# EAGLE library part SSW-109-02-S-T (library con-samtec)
THROUGH-HOLE .025" SQ POST SOCKET Source: Samtec SSW.pdf
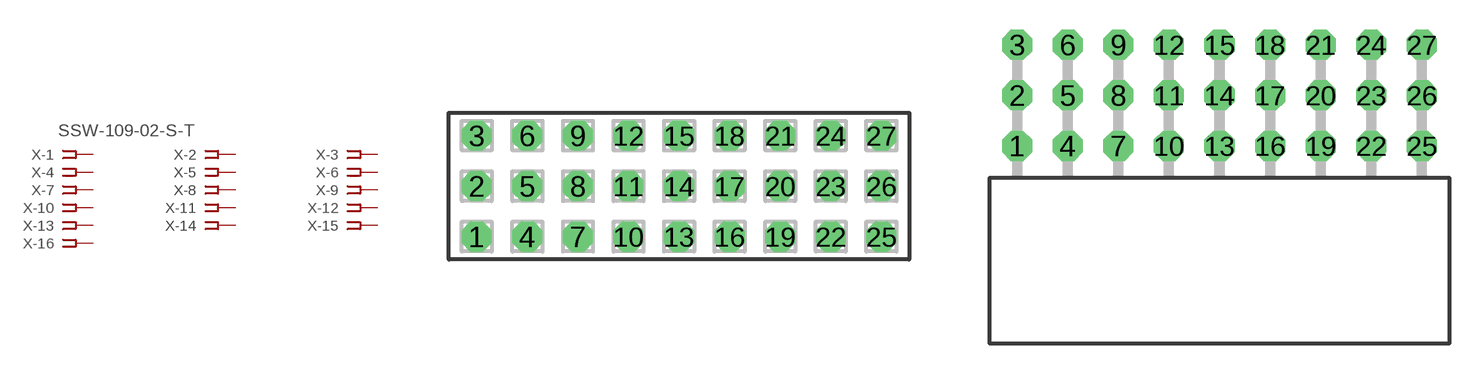
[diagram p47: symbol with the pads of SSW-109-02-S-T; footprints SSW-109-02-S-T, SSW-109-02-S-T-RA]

Designator prefix X; gates -1=FPINV -2=FPIN -3=FPIN -4=FPIN -5=FPIN -6=FPIN -7=FPIN -8=FPIN -9=FPIN -10=FPIN -11=FPIN -12=FPIN -13=FPIN -14=FPIN -15=FPIN -16=FPIN -17=FPIN -18=FPIN -19=FPIN -20=FPIN -21=FPIN -22=FPIN -23=FPIN -24=FPIN -25=FPIN -26=FPIN -27=FPIN

## SSW-109-02-S-T (MPN: SSW-109-02-S-T; OC_FARNELL: unknown; OC_NEWARK: 82P4801)  [SSW-109-02-S-T]
1  -1:1  pas
2  -2:1  pas
3  -3:1  pas
4  -4:1  pas
5  -5:1  pas
6  -6:1  pas
7  -7:1  pas
8  -8:1  pas
9  -9:1  pas
10  -10:1  pas
11  -11:1  pas
12  -12:1  pas
13  -13:1  pas
14  -14:1  pas
15  -15:1  pas
16  -16:1  pas
17  -17:1  pas
18  -18:1  pas
19  -19:1  pas
20  -20:1  pas
21  -21:1  pas
22  -22:1  pas
23  -23:1  pas
24  -24:1  pas
25  -25:1  pas
26  -26:1  pas
27  -27:1  pas

## SSW-109-02-S-TRA (MPN: SSW-109-02-S-T-RA; OC_FARNELL: unknown; OC_NEWARK: 82P4802)  [SSW-109-02-S-T-RA]
Pads as for SSW-109-02-S-T

## Footprint SSW-109-02-S-T (pad centres in mm)
THROUGH-HOLE .025" SQ POST SOCKET Source: Samtec SSW.pdf
drill 1 pad 1.5 octagon: 1 -10.16,-2.54; 2 -10.16,0; 3 -10.16,2.54; 4 -7.62,-2.54; 5 -7.62,0; 6 -7.62,2.54; 7 -5.08,-2.54; 8 -5.08,0; 9 -5.08,2.54; 10 -2.54,-2.54; 11 -2.54,0; 12 -2.54,2.54; 13 0,-2.54; 14 0,0; 15 0,2.54; 16 2.54,-2.54; 17 2.54,0; 18 2.54,2.54; 19 5.08,-2.54; 20 5.08,0; 21 5.08,2.54; 22 7.62,-2.54; 23 7.62,0; 24 7.62,2.54; 25 10.16,-2.54; 26 10.16,0; 27 10.16,2.54

## Footprint SSW-109-02-S-T-RA (pad centres in mm)
THROUGH-HOLE .025" SQ POST SOCKET Source: Samtec SSW.pdf
drill 1 pad 1.5 octagon: 1 -10.16,1.524; 2 -10.16,4.064; 3 -10.16,6.604; 4 -7.62,1.524; 5 -7.62,4.064; 6 -7.62,6.604; 7 -5.08,1.524; 8 -5.08,4.064; 9 -5.08,6.604; 10 -2.54,1.524; 11 -2.54,4.064; 12 -2.54,6.604; 13 0,1.524; 14 0,4.064; 15 0,6.604; 16 2.54,1.524; 17 2.54,4.064; 18 2.54,6.604; 19 5.08,1.524; 20 5.08,4.064; 21 5.08,6.604; 22 7.62,1.524; 23 7.62,4.064; 24 7.62,6.604; 25 10.16,1.524; 26 10.16,4.064; 27 10.16,6.604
